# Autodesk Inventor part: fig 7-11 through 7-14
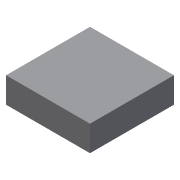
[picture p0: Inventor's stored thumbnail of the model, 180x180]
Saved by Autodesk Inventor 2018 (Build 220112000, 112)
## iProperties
Created: 2009-09
Part Number: fig 7-11 through 7-14
Document SubType Name: Modeling
Designer: Sham
Density: 1 g/cm^3
Material: Generic
Appearance: Default
Author: Sham
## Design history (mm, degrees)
sketch "Sketch1"
  geometry: L1 (-23, 20)-(0, 20); L2 (0, 20)-(0, -3); L3 (0, -3)-(-23, -3); L4 (-23, -3)-(-23, 20)
  constraints: 8 end point, 2 parallel, 1 horizontal, 1 perpendicular
  dimensions: "d2" = 23 distance of L1.start L1.end; "d3" = 23 distance of L3.end L1.start
extrude "Extrusion1" new body sketch "Sketch1" distance "d0" = 7; taper "d1" = 0 deg
body "Solid1"
